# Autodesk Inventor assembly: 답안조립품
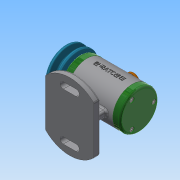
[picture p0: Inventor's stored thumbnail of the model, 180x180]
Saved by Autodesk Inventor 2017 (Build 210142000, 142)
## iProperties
Part Number: 답안조립품
Material: 일반
Document SubType Name: Assembly
Designer: user
Author: user
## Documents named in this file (14)
- C:\Users\user\Desktop\710906V1017\답안조립품.iam
- C:\Users\user\Desktop\710906V1017\본체.ipt
- C:\Users\user\Desktop\710906V1017\V벨트풀리.ipt
- C:\Users\user\Desktop\710906V1017\너트 M8.ipt
- C:\Users\user\Desktop\710906V1017\뒤커버.ipt
- C:\Users\user\Desktop\710906V1017\베어링 15x32x9.ipt
- C:\Users\user\Desktop\710906V1017\볼트 M4x12.ipt
- C:\Users\user\Desktop\710906V1017\스프링와셔 8.ipt
- C:\Users\user\Desktop\710906V1017\앞커버.ipt
- C:\Users\user\Desktop\710906V1017\오일 실 15x25x7.ipt
- C:\Users\user\Desktop\710906V1017\와셔 8x17.ipt
- C:\Users\user\Desktop\710906V1017\축.ipt
- C:\Users\user\Desktop\710906V1017\캡.ipt
- C:\Users\user\Desktop\710906V1017\키 3x3.ipt
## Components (1 placed, 1 different names)
1. V벨트풀리:1
